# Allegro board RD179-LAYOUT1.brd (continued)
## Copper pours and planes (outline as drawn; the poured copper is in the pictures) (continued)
VP+ on TOP: 44.98,16.75 44.95,16.76 44.93,16.77 44.27,17.43 44.26,17.45 44.25,17.48 44.25,17.72 44.26,17.75 44.27,17.77 44.98,18.48 45,18.49 45.03,18.5 47.67,18.5 47.73,18.48 47.75,18.43 47.75,16.82 47.73,16.77 47.67,16.75
N538933 on TOP: 33.33,17.9 33.27,17.92 33.25,17.98 33.25,22.15 33.27,22.2 33.33,22.23 35.94,22.23 35.97,22.22 36,22.2 37.7,20.5 39.79,20.5 39.82,20.49 39.85,20.48 40.12,20.2 43.42,20.2 43.48,20.18 43.5,20.12 43.5,19.07 43.48,19.02 43.42,19 42.15,19 41.07,17.92 41.05,17.91 41.02,17.9
N541275 on TOP: 4.58,30.5 4.52,30.52 4.5,30.57 4.5,33.42 4.52,33.48 4.58,33.5 9.68,33.5 9.73,33.48 9.75,33.42 9.75,30.57 9.73,30.52 9.68,30.5
N541304 on TOP: 4.58,19.5 4.52,19.52 4.5,19.57 4.5,22.43 4.52,22.48 4.58,22.5 11.93,22.5 11.98,22.48 12,22.43 12,19.57 11.98,19.52 11.93,19.5
N541340 on TOP: 4.58,41.5 4.52,41.52 4.5,41.58 4.5,44.42 4.52,44.48 4.58,44.5 11.68,44.5 11.73,44.48 11.75,44.42 11.75,41.58 11.73,41.52 11.68,41.5
N542318 on TOP: 4.58,71 4.52,71.02 4.5,71.08 4.5,73.92 4.52,73.98 4.58,74 11.68,74 11.73,73.98 11.75,73.92 11.75,71.08 11.73,71.02 11.68,71
N545140 on TOP: 42.7,27 42.65,27.02 42.62,27.07 42.62,34.62 40.75,36.5 36.78,36.5 36.75,36.51 36.73,36.52 35.02,38.23 35.01,38.25 35,38.28 35,42.42 35.02,42.48 35.08,42.5 38.55,42.5 38.57,42.5 38.59,42.49 40.72,41.45 43,40.75 43.02,40.75 43.03,40.73 43.48,40.29 43.49,40.27 43.5,40.24 43.5,27.07 43.48,27.02 43.42,27
N545527 on TOP: 40.08,26.2 40.05,26.21 40.03,26.22 32,34.25 27.82,34.25 27.77,34.27 27.75,34.33 27.75,38.17 27.77,38.23 27.82,38.25 32.72,38.25 32.75,38.24 32.77,38.23 36.5,34.5 40.72,34.5 40.75,34.49 40.77,34.48 41.1,34.15 41.12,34.12 41.12,34.09 41.12,26.27 41.1,26.22 41.05,26.2
N545615 on TOP: 33.58,3 33.52,3.02 33.5,3.08 33.5,7.42 33.52,7.48 33.58,7.5 36.67,7.5 36.73,7.48 36.75,7.42 36.75,5.5 37.25,5 41,5 42.25,6.25 42.25,11.62 42.26,11.65 42.27,11.67 42.3,11.7 42.3,12.12 42.32,12.18 42.38,12.2 43.38,12.2 43.43,12.18 43.45,12.12 43.45,11.7 43.68,11.47 43.69,11.45 43.7,11.42 43.7,5.23 43.69,5.2 43.68,5.18 41.52,3.02 41.5,3.01 41.47,3
N16827190 on TOP: 27.82,39.5 27.77,39.52 27.75,39.58 27.75,43.92 27.77,43.98 27.82,44 32.92,44 32.98,43.98 33,43.92 33,39.58 32.98,39.52 32.92,39.5
N16827301 on TOP: 26.32,4.5 26.27,4.52 26.25,4.58 26.25,7.42 26.27,7.48 26.32,7.5 31.18,7.5 31.23,7.48 31.25,7.42 31.25,4.58 31.23,4.52 31.18,4.5

Small or netless copper shapes (teardrops, artwork), in the pictures only: 118 on TOP, 110 on BOTTOM

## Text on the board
PAGE_OUTLINE: K | 1 | R10 | R12 | R11 | SJP3 | + | SJP4 | R2 | R4 | R1 | R3 | U1 | C8 | LEDP1 | R43 | D1 | J3 | TP11 | R46 | C34 | C19 | TP13 | C36 | R39 | C33 | TP9 | R33 | L1 | R29 | C30 | U2 | R35 | C6 | U6 | R16 | U8 | C7 | C18 | TP8 | TP7 | U5 | R54 | C26 | C31 | C11 | TP10 | TP12 | J10 | C16 | C21 | C20 | C24 | R18 | TP6 | U7 | S_SW1 | TST1 | R50 | TST2 | R51 | S_SW2 | TST3 | C38 | C25 | R52 | S_SW3 | S_SW4 | R53 | J4 | JP1 | 2 | 3 | J2 | J1 | L4 | L3 | L2 | F1 | SJP2 | C12 | C9 | SJP1 | C10 | R5 | C37 | R48 | C35 | C2 | C1 | TP5 | R13 | C15 | R17 | C32 | C14 | C3 | TP14 | SW1 | R45 | R37 | R44 | R47 | TP4 | R49 | D6 | R42 | TP15 | R41 | D2 | R38 | C27 | D5 | TP3 | R14 | R28 | R32 | R34 | TP16 | R27 | D4 | C4 | C13 | R7 | TP1 | R6 | J7 | C5 | Y1 | R19 | C22 | 7 | J6 | 8 | J9 | C29 | LED1 | R25 | VR1 | LED2 | R30 | LED3 | R36 | LEDP2 | R15 | C39 | C40 | R22 | 19 | 5 | J8 | J5 | 20 | DC INPUT | 120-340V | GND | FUSE 440V-10A | EXT.CONTROL | 4164F | - | METIS- | U | W | V | AD_W | UH | EMG | AVDD | UL | RESET | VH | VL | WH | DVDD | AD_V | WL | AD_U | AVSS | DVSS | RELAY | EXT.DAC | BOOT | DC15V | DEBUG | DC5V | METIS-4164F | SWD
